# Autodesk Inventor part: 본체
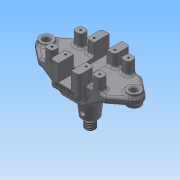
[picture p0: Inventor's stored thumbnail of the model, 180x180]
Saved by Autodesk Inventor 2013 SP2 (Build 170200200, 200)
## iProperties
Created: 2025-07
Part Number: 본체
Material: Generic
Document SubType Name: Modeling
Designer: a
Density: 1 g/cm^3
Author: a
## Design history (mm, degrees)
sketch "스케치1"
  geometry: L1 (-41.804, 23)-(41.804, 23); L2 (41.804, 23)-(41.804, -23); L3 (41.804, -23)-(-41.804, -23); L4 (-41.804, -23)-(-41.804, 23); L5 (-41.804, 23)-(41.804, -23); L6 (41.804, 23)-(-41.804, -23); L7 (41.804, -23)-(61.157, -7.88); L8 (61.157, 7.88)-(41.804, 23); L9 (-41.804, -23)-(-61.157, -7.88); L10 (-41.804, 23)-(-61.157, 7.88); A1 r 10 centre (55, 0) between (61.157, -7.88) and (61.157, 7.88); A2 r 10 centre (-55, 0) between (-61.157, -7.88) and (-61.157, 7.88); 3 further points
  constraints: 20 end point, 4 midpoint, 4 point on circle, 4 tangent, 2 centre point, 2 horizontal alignment, 2 parallel, 1 horizontal, 1 perpendicular
  dimensions: "d0" = 46 distance of L3.end L1.start; "d4" = 110 distance of A2.centre A1.centre; "d5" = 55 distance of point (0, 0) A2.centre; "d6" = 76 deg angle of L10 L9; "d7" = 76 deg angle of L8 L7; "d8" = 20 diameter of A1
extrude "돌출1" new body sketch "스케치1" stored distance "d9" = 9; taper "d10" = 0 deg
sketch "스케치2"
  geometry: C1 r 8 at (-55, 0); C2 r 8 at (55, 0); A1 r 10 centre (-55, 0) between (-61.157, 7.88) and (-61.157, -7.88) reference; A2 r 10 centre (55, 0) between (61.157, -7.88) and (61.157, 7.88) reference; 1 further point
  constraints: 2 centre point, 2 coincident
  dimensions: "d11" = 16 diameter of C1; "d13" = 16 diameter of C2
extrude "돌출2" join sketch "스케치2" distance "d14" = 3; taper "d15" = 0 deg
extrude "돌출3" join sketch "스케치2" distance "d16" = 12; taper "d17" = 0 deg
hole "구멍1" diameter "d20" = 8; stored, may be unused: countersink angle "d24" = 90 deg, drill point angle "d26" = 118 deg; dims "d18" = 10, "d19" = 10, "d21" = 6, "d22" = 4, "d23" = 2, "d25" = 8
hole "구멍2" diameter "d29" = 8; stored, may be unused: countersink angle "d33" = 90 deg, drill point angle "d35" = 118 deg; dims "d27" = 10, "d28" = 10, "d30" = 6, "d31" = 4, "d32" = 2, "d34" = 8
chamfer "모따기1" distance "d36" = 1; stored, may be unused: second distance "d37" = 2, angle "d38" = 45 deg
chamfer "모따기2" distance "d39" = 1; stored, may be unused: second distance "d40" = 2, angle "d41" = 45 deg
chamfer "모따기3" distance "d42" = 1; stored, may be unused: second distance "d43" = 2, angle "d44" = 45 deg
chamfer "모따기4" distance "d45" = 1; stored, may be unused: second distance "d46" = 2, angle "d47" = 45 deg
sketch "스케치3"
  geometry: L1 (-41.804, -23)-(41.804, -23) reference; L2 (41.804, 23)-(-41.804, 23) reference; L3 (-35, -23)-(-25, -23); L4 (-25, -23)-(-25, -13); L5 (-25, -13)-(-35, -13); L6 (-35, -13)-(-35, -23); L7 (0, 23)-(0, -23); L8 (-55, 0)-(55, 0); L9 (-30, -13)-(-30, -23); L10 (-35, -18)-(-25, -18); L11 (61.157, -7.88)-(41.804, -23); L12 (25, -13)-(35, -13); L13 (35, -13)-(35, -23); L14 (35, -18)-(25, -18); L15 (30, -13)-(30, -23); L16 (25, -23)-(25, -13); L17 (35, -23)-(25, -23); L18 (41.804, -23)-(-41.804, -23); L19 (-25, 23)-(-25, 13); L20 (-30, 13)-(-30, 23); L21 (-25, 13)-(-35, 13); L22 (-35, 13)-(-35, 23); L23 (-35, 23)-(-25, 23); L24 (-35, 18)-(-25, 18); L25 (30, 13)-(30, 23); L26 (25, 13)-(35, 13); L27 (35, 13)-(35, 23); L28 (35, 18)-(25, 18); L29 (35, 23)-(25, 23); L30 (25, 23)-(25, 13); L31 (0, -23)-(0, 23); L32 (-41.804, 23)-(41.804, 23); L33 (41.804, 23)-(-41.804, 23); A1 r 10 centre (-55, 0) between (-61.157, 7.88) and (-61.157, -7.88) reference; A2 r 10 centre (55, 0) between (61.157, -7.88) and (61.157, 7.88) reference; 1 further point
  constraints: 62 end point, 32 symmetric about line, 6 midpoint, 4 point on line, 2 parallel, 2 perpendicular, 1 horizontal
  dimensions: "d48" = 10 distance of L4.end L5.end; "d50" = 10 distance of L3.end L4.end; "d51" = 30 distance between parallel lines of L7 L9
extrude "돌출4" join sketch "스케치3" distance "d52" = 16; taper "d53" = 0 deg
sketch "스케치4"
  geometry: L1 (-18, 32)-(18, 32); L2 (18, 32)-(18, 13); L3 (18, 13)-(-18, 13); L4 (-18, 13)-(-18, 32); L5 (-18, -13)-(18, -13); L6 (18, -13)-(18, -32); L7 (18, -32)-(-18, -32); L8 (-18, -32)-(-18, -13); 3 further points
  constraints: 16 end point, 4 parallel, 2 horizontal, 2 midpoint, 2 perpendicular, 2 vertical alignment
  dimensions: "d54" = 36 distance of L1.start L1.end; "d56" = 36 distance of L6.end L7.end; "d57" = 64 distance between parallel lines of L7 L1; "d58" = 32 distance of point (0, 0) point (0, 32); "d59" = 26 distance between parallel lines of L5 L3; "d60" = 13 distance from line of point (0, 0) L3
extrude "돌출5" join sketch "스케치4" distance "d61" = 16; taper "d63" = 0 deg; dims "d62" = 15, "d64" = 0
sketch "스케치5"
  geometry: L1 (0, 0)-(36, 0) reference; L2 (10, 0)-(26, 0); L3 (26, 0)-(26, -21); L4 (26, -21)-(10, -21); L5 (10, -21)-(10, 0); 2 further points
  constraints: 8 end point, 2 midpoint, 2 parallel, 1 horizontal, 1 perpendicular, 1 vertical alignment
  dimensions: "d65" = 16 distance of L2.start L2.end; "d67" = 21 distance of L4.end L2.start
extrude "돌출6" cut sketch "스케치5" stored distance "d68" = 16; taper "d69" = 0 deg
sketch "스케치6"
  geometry: L1 (60, -7.5)-(59, -6.5) reference; L2 (59, -6.5)-(59, 6.5) reference; L3 (59, 6.5)-(60, 7.5) reference; L4 (60, 7.5)-(63, 7.5) reference; L5 (63, 7.5)-(63, 4.5) reference; L6 (63, 4.5)-(65, 4.5) reference; L7 (65, 4.5)-(65, -4.5) reference; L8 (65, -4.5)-(63, -4.5) reference; L9 (63, -4.5)-(63, -7.5) reference; L10 (63, -7.5)-(60, -7.5) reference; L11 (-59, -6.5)-(-60, -7.5) reference; L12 (-60, -7.5)-(-63, -7.5) reference; L13 (-63, -7.5)-(-63, -4.5) reference; L14 (-63, -4.5)-(-65, -4.5) reference; L15 (-65, -4.5)-(-65, 4.5) reference; L16 (-65, 4.5)-(-63, 4.5) reference; L17 (-63, 4.5)-(-63, 7.5) reference; L18 (-63, 7.5)-(-60, 7.5) reference; L19 (-60, 7.5)-(-59, 6.5) reference; L20 (-59, 6.5)-(-59, -6.5) reference; L21 (-50, -7.5)-(-51, -6.5) reference; L22 (-51, -6.5)-(-51, 6.5) reference; L23 (-51, 6.5)-(-50, 7.5) reference; L24 (-50, 7.5)-(-47, 7.5) reference; L25 (-47, 7.5)-(-47, 4.5) reference; L26 (-47, 4.5)-(-8, 4.5) reference; L27 (-8, 4.5)-(-8, -0.5) reference; L28 (-8, -0.5)-(8, -0.5) reference; L29 (8, -0.5)-(8, 4.5) reference; L30 (8, 4.5)-(47, 4.5) reference; L31 (47, 4.5)-(47, 7.5) reference; L32 (47, 7.5)-(50, 7.5) reference; L33 (50, 7.5)-(51, 6.5) reference; L34 (51, 6.5)-(51, -6.5) reference; L35 (51, -6.5)-(50, -7.5) reference; L36 (50, -7.5)-(47, -7.5) reference; L37 (47, -7.5)-(47, -4.5) reference; L38 (47, -4.5)-(-47, -4.5) reference; L39 (-47, -4.5)-(-47, -7.5) reference; L40 (-47, -7.5)-(-50, -7.5) reference; L41 (-38.85, -4.5)-(-16, -20.5); L42 (-16, -20.5)-(16, -20.5); L43 (16, -20.5)-(38.85, -4.5); L44 (25, 20.5)-(35, 20.5) reference; L45 (-38.85, -4.5)-(38.85, -4.5); 2 further points
  constraints: 8 end point, 2 point on line, 1 collinear, 1 midpoint, 1 parallel, 1 vertical alignment
  dimensions: "d70" = 41 distance between parallel lines of L44 L42; "d71" = 35 deg angle of L42 L43; "d72" = 35 deg angle of L42 L41; "d73" = 32 distance of L41.end L42.end
extrude "돌출7" join sketch "스케치6" stored distance "d74" = 46; taper "d75" = 0 deg
sketch "스케치7"
  geometry: L1 (-10.5, 23)-(-10.5, 32) reference; L2 (-10.5, 32)-(-0.5, 32) reference; L3 (-0.5, 32)-(-0.5, -32) reference; L4 (-0.5, -32)-(-10.5, -32) reference; L5 (-10.5, -32)-(-10.5, -23) reference; L6 (-10.5, -23)-(-20.5, -23) reference; L7 (-20.5, -23)-(-20.5, 23) reference; L8 (-20.5, 23)-(-10.5, 23) reference; L9 (-20.5, 0)-(-47.5, 0); L10 (-20.5, 12.5)-(-24.5, 12.5); L11 (-24.5, 12.5)-(-47.5, 10); L12 (-47.5, 10)-(-47.5, 0); L13 (-20.5, 12.5)-(-20.5, 0); 1 further point
  constraints: 10 end point, 3 parallel, 1 midpoint, 1 perpendicular, 1 point on line
  dimensions: "d76" = 25 diameter of L10 L9; "d78" = 4 distance of L10.start L10.end; "d79" = 23 horizontal distance of L11.end L10.end; "d80" = 20 diameter of L11.end L9
revolve "회전1" sketch "스케치7" stored, may be unused: angle "d81" = 90 deg
sketch "스케치8"
  geometry: L1 (-10.5, 23)-(-10.5, 32) reference; L2 (-10.5, 32)-(-0.5, 32) reference; L3 (-0.5, 32)-(-0.5, -32) reference; L4 (-0.5, -32)-(-10.5, -32) reference; L5 (-10.5, -32)-(-10.5, -23) reference; L6 (-10.5, -23)-(-20.5, -23) reference; L7 (-20.5, -23)-(-20.5, -12.5) reference; L8 (-20.5, -12.5)-(-24.5, -12.5) reference; L9 (-24.5, -12.5)-(-47.5, -10) reference; L10 (-47.5, -10)-(-47.5, 10) reference; L11 (-47.5, 10)-(-24.5, 12.5) reference; L12 (-24.5, 12.5)-(-20.5, 12.5) reference; L13 (-20.5, 12.5)-(-20.5, 23) reference; L14 (-20.5, 23)-(-10.5, 23) reference; L15 (-47.5, 0)-(-61.5, 0); L16 (-47.5, 0)-(-47.5, 4.7); L17 (-47.5, 4.7)-(-50.5, 4.7); L18 (-50.5, 4.7)-(-52.752, 6); L19 (-52.752, 6)-(-61.5, 6); L20 (-61.5, 6)-(-61.5, 0); 1 further point
  constraints: 12 end point, 2 parallel, 2 perpendicular, 1 midpoint, 1 point on line
  dimensions: "d82" = 3 distance of L16.end L17.end; "d84" = 30 deg angle of L19 L18; "d86" = 9.4 diameter of L17 L15; "d87" = 41 distance between parallel lines of L13 L20; "d89" = 12 diameter of L19 L15
revolve "회전2" sketch "스케치8" stored, may be unused: angle "d90" = 90 deg
chamfer "모따기5" distance "d91" = 1; stored, may be unused: second distance "d92" = 2, angle "d93" = 45 deg
feature "스레드1" dims "d94" = 10, "d95" = 0
sketch "스케치9"
  geometry: L1 (-10.5, 23)-(-10.5, 32) reference; L2 (-10.5, 32)-(-0.5, 32) reference; L3 (-0.5, 32)-(-0.5, -32) reference; L4 (-0.5, -32)-(-10.5, -32) reference; L5 (-10.5, -32)-(-10.5, -23) reference; L6 (-10.5, -23)-(-20.5, -23) reference; L7 (-20.5, -23)-(-20.5, -12.5) reference; L8 (-20.5, -12.5)-(-24.5, -12.5) reference; L9 (-24.5, -12.5)-(-47.5, -10) reference; L10 (-47.5, -10)-(-47.5, -4.7) reference; L11 (-47.5, -4.7)-(-50.5, -4.7) reference; L12 (-50.5, -4.7)-(-52.752, -6) reference; L13 (-52.752, -6)-(-60.5, -6) reference; L14 (-60.5, -6)-(-61.5, -5) reference; L15 (-61.5, -5)-(-61.5, 5) reference; L16 (-61.5, 5)-(-60.5, 6) reference; L17 (-60.5, 6)-(-52.752, 6) reference; L18 (-52.752, 6)-(-50.5, 4.7) reference; L19 (-50.5, 4.7)-(-47.5, 4.7) reference; L20 (-47.5, 4.7)-(-47.5, 10) reference; L21 (-47.5, 10)-(-24.5, 12.5) reference; L22 (-24.5, 12.5)-(-20.5, 12.5) reference; L23 (-20.5, 12.5)-(-20.5, 23) reference; L24 (-20.5, 23)-(-10.5, 23) reference; L25 (-27.617, 12.161)-(-27.185, 8.185); L26 (-27.185, 8.185)-(-43.091, 6.456); L27 (-43.091, 6.456)-(-43.523, 10.432); L28 (-27.617, 12.161)-(-43.523, 10.432); 1 further point
  constraints: 8 end point, 2 perpendicular, 2 point on line, 1 collinear, 1 parallel
  dimensions: "d96" = 4 distance between parallel lines of L21 L26; "d97" = 16 distance between parallel lines of L27 L25; "d98" = 4 distance from line of L20.end L27
extrude "돌출8" cut sketch "스케치9" stored distance "d99" = 7; taper "d100" = 0 deg
fillet "모깎기1" dims "d101" = 3.5
fillet "모깎기2" dims "d102" = 3
fillet "모깎기3" dims "d103" = 3
fillet "모깎기4" dims "d104" = 3
fillet "모깎기6" dims "d106" = 3
fillet "모깎기7" dims "d107" = 3
fillet "모깎기8" dims "d108" = 3
fillet "모깎기9" dims "d109" = 3
fillet "모깎기10" dims "d110" = 3
fillet "모깎기11" dims "d111" = 3
fillet "모깎기12" dims "d112" = 3
fillet "모깎기13" dims "d113" = 3
fillet "모깎기14" dims "d114" = 3
fillet "모깎기15" dims "d115" = 3
sketch "스케치10"
  geometry: 2 further points
  dimensions: "d116" = 13 horizontal distance of point (0, 0) point (-13, -18); "d117" = 18 vertical distance of point (-13, -18) point (0, 0)
hole "구멍3" sketch "스케치10" at (-13, -18) diameter "d118" = 2.459; stored, may be unused: countersink angle "d122" = 90 deg, drill point angle "d124" = 118 deg; dims "d119" = 6, "d120" = 4, "d121" = 2, "d123" = 8
sketch "스케치11"
  geometry: L1 (-25, -20)-(-25, -16) reference; L2 (-28, -13)-(-32, -13) reference; 2 further points
  dimensions: "d131" = 5 distance from line of L1 point (-30, -18); "d132" = 5 distance from line of L2 point (-30, -18)
hole "구멍4" sketch "스케치11" at (-30, -18) diameter "d133" = 2.459; stored, may be unused: countersink angle "d137" = 90 deg, drill point angle "d139" = 118 deg; dims "d134" = 6, "d135" = 4, "d136" = 2, "d138" = 8
fillet "모깎기16" dims "d140" = 3
sketch "스케치12"
  geometry: L1 (16, 0)-(0, 0) reference; L2 (-7, 21)-(0, 21) reference; 3 further points
  constraints: 1 midpoint, 1 vertical alignment, 1 other
  dimensions: "d141" = 24 distance from line of L2 point (8, -3)
feature "엠보싱1" sketch "스케치12" dims "d4" = 110, "d142" = 0.5, "d143" = 0
node "솔리드1"
pattern_linear "직사각형 패턴1" dims "d127" = 26
pattern_linear "직사각형 패턴2" dims "d130" = 36
mirror "대칭1"
mirror "대칭2"
node "절단 모서리 투영1"
node "절단 모서리 투영2"
node "절단 모서리 투영3"
node "절단 모서리 투영4"
